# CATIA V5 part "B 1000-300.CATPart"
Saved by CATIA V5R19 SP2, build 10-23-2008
Part number: B 1000-300
Bounding box of the stored display mesh (mm): x -24.865 to 24.865, y -24.997 to 24.997, z 0 to 695
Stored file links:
  C:\Users\Bora\Desktop\3D Katı model\B serisi\B 1000\B 1000-300.CATPart
  C:\Program Files\Dassault Systemes\B19\intel_a\reffiles\standard\MetricThickPitch.txt
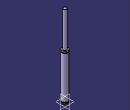
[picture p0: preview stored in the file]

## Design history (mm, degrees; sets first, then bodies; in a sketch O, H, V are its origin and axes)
Body1 (main body)
  Sketch1 on yz-plane, origin (0, 0, 0), H (0, 1, 0), V (0, 0, 1)
    point P1 (25, 379.5)
    point P2 (25, 375.5)
    point P3 (25, 379.5)
    point P6 (25, 375.5)
    point P9 (15, 694)
    point P11 (15, 694)
    arc A1 centre (25, 377.5) radius 2 from (25, 379.5) to (25, 375.5) ccw
    line L1 (25, 379.5) -> (25, 392)
    line L2 (25, 13) -> (25, 375.5)
    line L3 (21.5, 13) -> (21.5, 8)
    arc A2 centre (14, 694) radius 1 from (15, 694) to (14, 695) ccw
    line L4 (15, 694) -> (15, 392)
    line L5 (25, 0) -> (25, 8)
    line L6 (14, 695) -> (0, 695)
    point P15 (0, 695)
    line L7 (15, 392) -> (25, 392)
    line L8 (0, 0) -> (25, 0)
    line L9 (21.5, 13) -> (25, 13)
    line L10 (21.5, 8) -> (25, 8)
    coincidence: P15 V, P1 P3, P2 P6, P9 P11
    tangency: L6 A2
    horizontal: L7 H, L8 H, L9 H, L10 H
  Shaft1: profile Sketch1, axis Sketch1.V, angle 360
  Sketch2 on face of Shaft1 from Sketch1.L8, origin (0, 0, 0), H (1, 0, 0), V (0, -1, 0)
    point P1 (10, 0)
    distance P1 V = 10
  Hole1: placed by Sketch2, at (10, 0, 0) direction (0, 0, 1), diameter 6.647, depth 13, threaded "M8", thread diameter 8, thread depth 13, pitch 1.25
  CircPattern1: of Hole1, instances 2, angular step 180, axis from xy-plane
